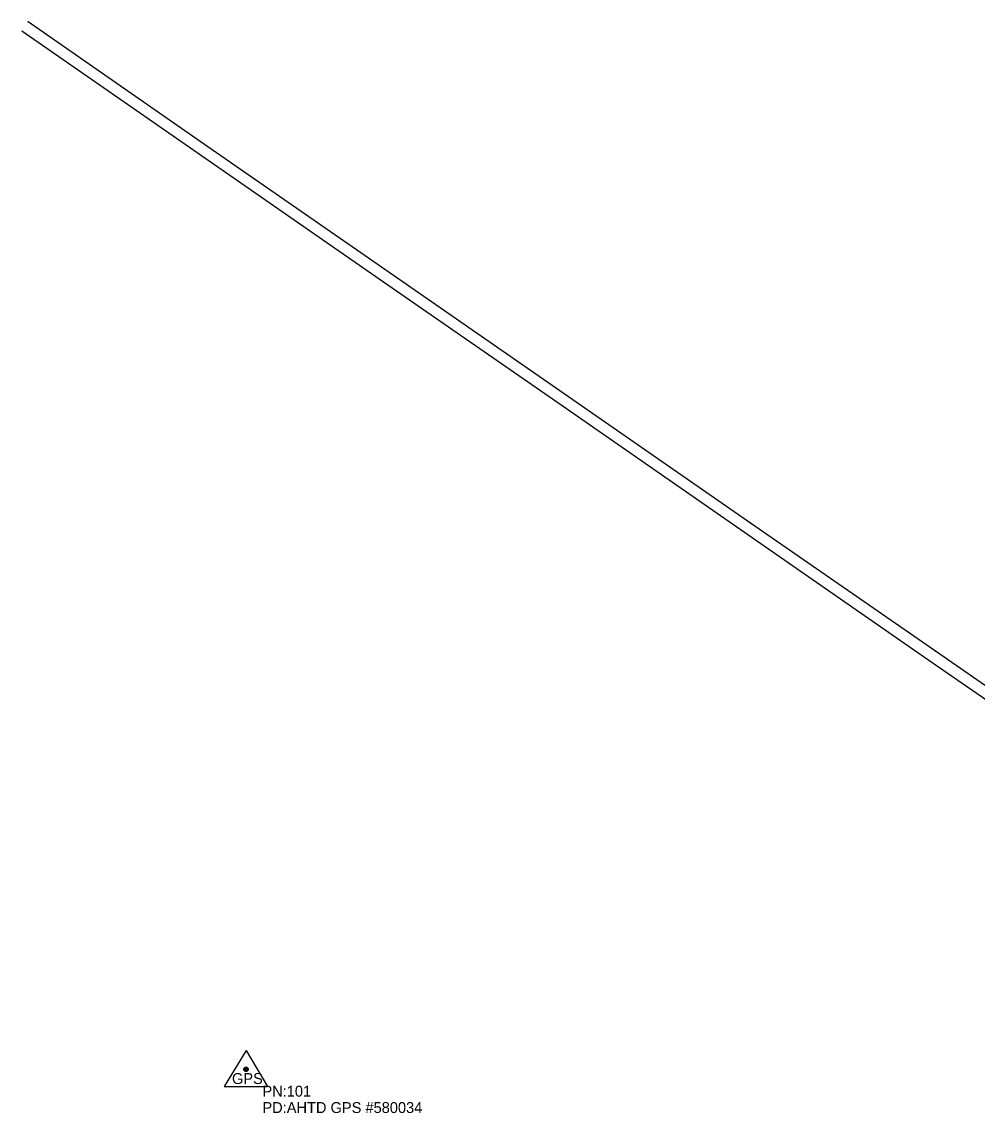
# Model space of a CAD drawing. Extents: x 997398 to 1003416, y 334596 to 337085.
# Drawn here: x 998581.6 to 999019.1, y 336132.5 to 336632.4 of the extents above; entities that cross this region are included whole.
import ezdxf

# ---------------------------------------------------------------- set-up
doc = ezdxf.new("R2010")
doc.units = 0
for name, color, linetype in [('S_MSC_PT_SYM', 7, 'Continuous'), ('S_PRIMARY_CTL', 7, 'Continuous'), ('S_PRIMARY_CTL_ANNOT', 7, 'Continuous'), ('S_RAILROAD', 7, 'Continuous')]:
    doc.layers.add(name, color=color, linetype=linetype)

msp = doc.modelspace()

# ---------------------------------------------------------------- linework, layer by layer
at = {"layer": 'S_MSC_PT_SYM'}
for points in [[(998584.47, 336632.35), (998584.47, 336632.4), (998584.47, 336632.35), (998584.42, 336632.35), (998584.47, 336632.35), (998584.47, 336632.3), (998584.47, 336632.35), (998584.52, 336632.35)], [(998581.68, 336628.27), (998581.68, 336628.32), (998581.68, 336628.27), (998581.63, 336628.27), (998581.68, 336628.27), (998581.68, 336628.22), (998581.68, 336628.27), (998581.73, 336628.27)], [(998666.81, 336575.14), (998666.81, 336575.19), (998666.81, 336575.14), (998666.76, 336575.14), (998666.81, 336575.14), (998666.81, 336575.09), (998666.81, 336575.14), (998666.86, 336575.14)], [(998663.83, 336571.18), (998663.83, 336571.23), (998663.83, 336571.18), (998663.78, 336571.18), (998663.83, 336571.18), (998663.83, 336571.13), (998663.83, 336571.18), (998663.88, 336571.18)], [(998750.26, 336517.29), (998750.26, 336517.34), (998750.26, 336517.29), (998750.21, 336517.29), (998750.26, 336517.29), (998750.26, 336517.24), (998750.26, 336517.29), (998750.31, 336517.29)], [(998747.26, 336513.36), (998747.26, 336513.41), (998747.26, 336513.36), (998747.21, 336513.36), (998747.26, 336513.36), (998747.26, 336513.31), (998747.26, 336513.36), (998747.31, 336513.36)], [(998831.95, 336460.68), (998831.95, 336460.73), (998831.95, 336460.68), (998831.9, 336460.68), (998831.95, 336460.68), (998831.95, 336460.63), (998831.95, 336460.68), (998832, 336460.68)], [(998829.06, 336456.59), (998829.06, 336456.64), (998829.06, 336456.59), (998829.01, 336456.59), (998829.06, 336456.59), (998829.06, 336456.54), (998829.06, 336456.59), (998829.11, 336456.59)], [(998915.27, 336402.81), (998915.27, 336402.86), (998915.27, 336402.81), (998915.22, 336402.81), (998915.27, 336402.81), (998915.27, 336402.76), (998915.27, 336402.81), (998915.32, 336402.81)], [(998912.5, 336398.64), (998912.5, 336398.69), (998912.5, 336398.64), (998912.45, 336398.64), (998912.5, 336398.64), (998912.5, 336398.59), (998912.5, 336398.64), (998912.55, 336398.64)], [(998999.95, 336344.09), (998999.95, 336344.14), (998999.95, 336344.09), (998999.9, 336344.09), (998999.95, 336344.09), (998999.95, 336344.04), (998999.95, 336344.09), (999000, 336344.09)], [(998997.03, 336340), (998997.03, 336340.05), (998997.03, 336340), (998996.98, 336340), (998997.03, 336340), (998997.03, 336339.95), (998997.03, 336340), (998997.08, 336340)]]:
    msp.add_lwpolyline(points, dxfattribs=at)
at = {"layer": 'S_PRIMARY_CTL'}
for p, q in [((998684.3, 336161.28), (998674.27, 336144.77)), ((998684.3, 336161.28), (998694.12, 336144.77)), ((998674.27, 336144.77), (998694.12, 336144.77))]:
    msp.add_line(p, q, dxfattribs=at)
for radius in [1.04, 0.609, 0.344]:
    msp.add_circle((998684.3, 336152.58), radius, dxfattribs=at)
at = {"layer": 'S_RAILROAD'}
for p, q in [((998666.81, 336575.14), (998584.47, 336632.35)), ((998581.68, 336628.27), (998663.83, 336571.18)), ((998750.26, 336517.29), (998666.81, 336575.14)), ((998663.83, 336571.18), (998747.26, 336513.36)), ((998831.95, 336460.68), (998750.26, 336517.29)), ((998747.26, 336513.36), (998829.06, 336456.59)), ((998915.27, 336402.81), (998831.95, 336460.68)), ((998829.06, 336456.59), (998912.5, 336398.64)), ((998999.95, 336344.09), (998915.27, 336402.81)), ((998912.5, 336398.64), (998997.03, 336340)), ((999081.98, 336287.15), (998999.95, 336344.09)), ((998997.03, 336340), (999079.25, 336282.97))]:
    msp.add_line(p, q, dxfattribs=at)

# ---------------------------------------------------------------- texts
at = {"layer": 'S_PRIMARY_CTL'}
msp.add_text('GPS', height=5, rotation=360, dxfattribs=at).set_placement((998677.86, 336145.87))
at = {"layer": 'S_PRIMARY_CTL_ANNOT'}
for s, p in [('PN:101', (998691.8, 336140.08)), ('PD:AHTD GPS #580034', (998691.8, 336132.58))]:
    msp.add_text(s, height=5, dxfattribs=at).set_placement(p)

doc.saveas('drawing.dxf')
